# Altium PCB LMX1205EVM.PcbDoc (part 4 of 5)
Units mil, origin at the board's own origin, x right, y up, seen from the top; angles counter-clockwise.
Board outline 5000 x 5000 mil, 6 copper layers (Top Layer, RF GND, Signal Layer 3, Signal Layer 4, Signal Layer 5, Bottom Layer), stack 61.6 mil thick; 176 components, 99 nets, 572 pads, 2473 vias.
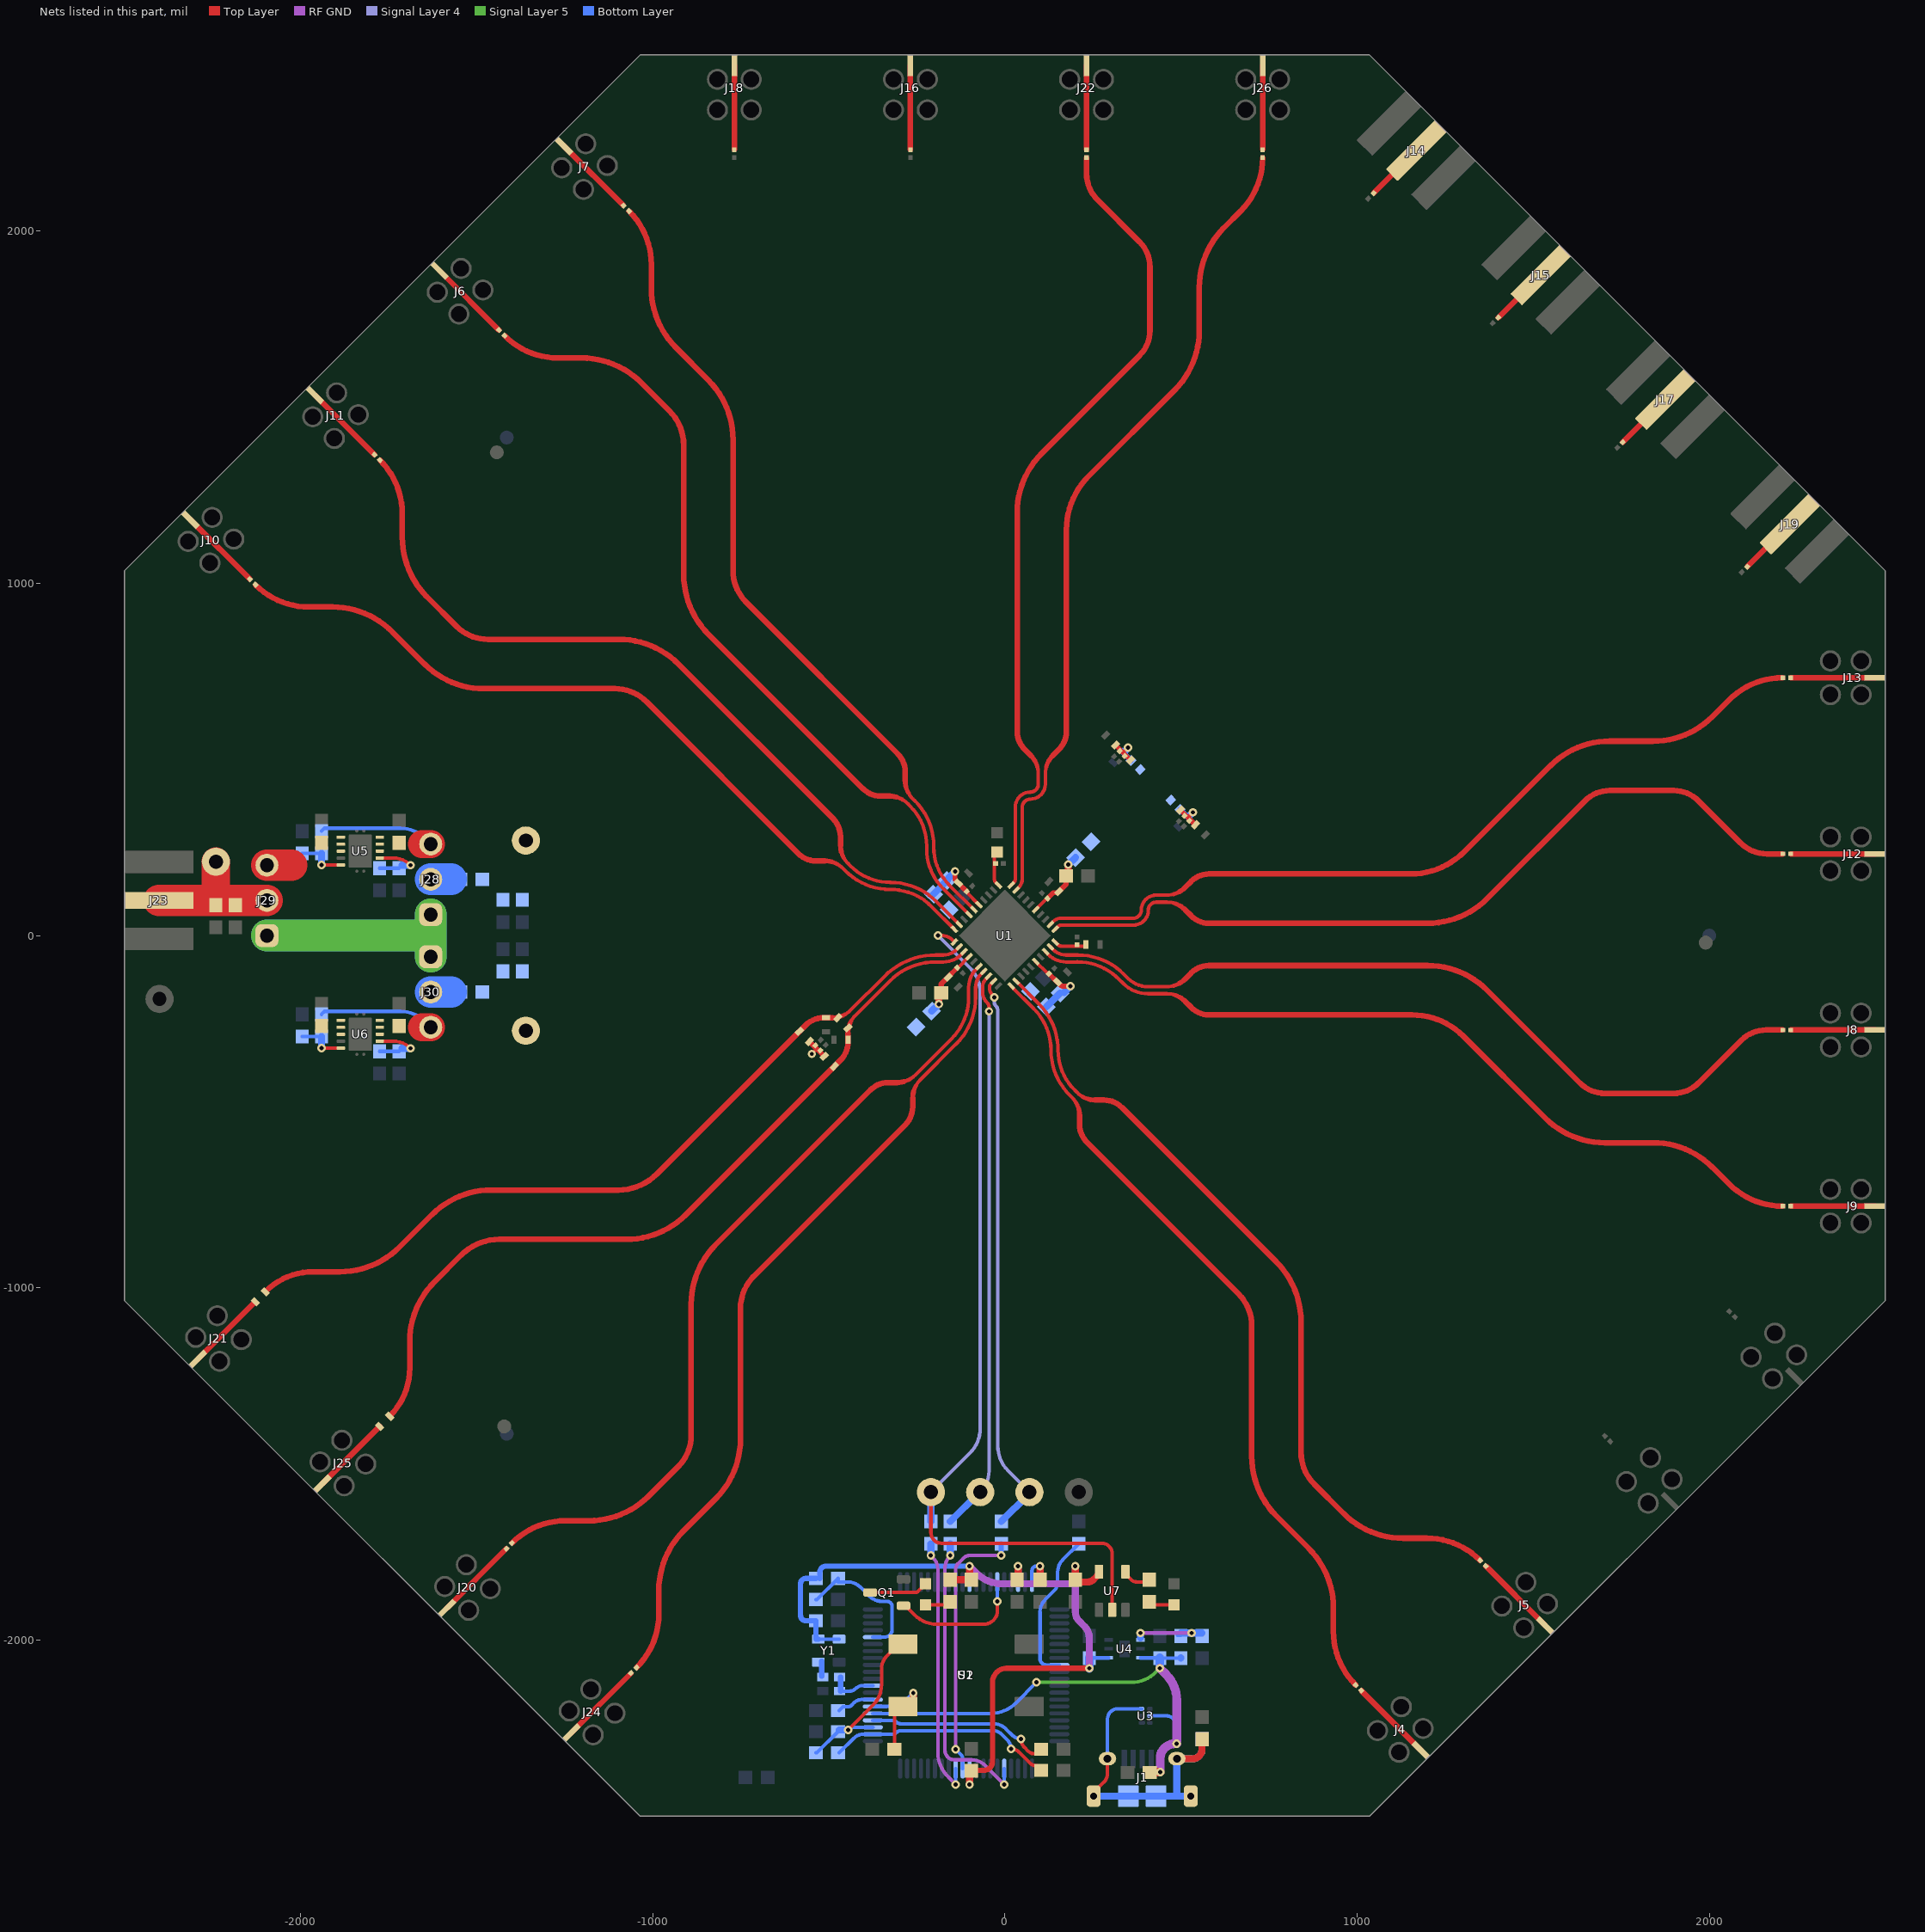
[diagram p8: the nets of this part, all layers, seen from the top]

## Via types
v1: diameter 24, hole 12, Top Layer to Bottom Layer, tented both sides, 2320 vias
v2: diameter 28, hole 16, Top Layer to Bottom Layer, 120 vias
v3: diameter 19.68, hole 7.87, Top Layer to Bottom Layer, tented both sides, 29 vias
v4: diameter 24, hole 12, Top Layer to Bottom Layer, tented bottom, 3 vias
v5: diameter 236.22, hole 157.48, Top Layer to Bottom Layer, tented both sides, 1 vias

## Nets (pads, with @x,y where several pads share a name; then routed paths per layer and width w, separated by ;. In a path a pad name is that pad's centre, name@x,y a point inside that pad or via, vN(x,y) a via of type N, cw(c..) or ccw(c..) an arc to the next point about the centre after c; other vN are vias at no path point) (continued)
NetC3_1: C3.1 C4.1 U1.31 | length 91.3
  Top Layer w10: C4.1@-29.67,230.48 -29.67,160.48 ccw(c-16.3,160.48) -25.75,151.03 U1.31@-18.1,143.37
NetC5_1: C5.1 C6.1 U1.20 | length 95.5
  Top Layer w10: U1.20@143.37,-18.1 151.03,-25.75 ccw(c160.48,-16.3) 160.48,-29.67 230,-29.67 C6.1@230,-25
NetC8_1: C8.1 C9.1 C70.2 L4.2 U1.25 | length 201.5
  Top Layer w10: U1.25@87.69,73.77 C8.1@120.1,106.18
  Top Layer w14: C8.1@120.93,105.34 137.2,121.61 C9.1@149.89,121.61 ; C70.2@173.56,169.71 C70.2@180.31,169.71
  Top Layer w15: C9.1@153.44,125.16 173.56,145.28 C70.2@173.56,169.71
  Top Layer w20: C70.2@180.31,169.71 v1(180.31,201.53)
  Bottom Layer w20: v1(180.31,201.53) L4.2@200.47,221.68
NetC10_1: C10.1 C11.1 C71.2 L3.2 U1.4 | length 197
  Top Layer w10: C10.1@-134.02,-92.26 U1.4@-101.61,-59.85
  Top Layer w14: C11.1@-161.95,-118.07 -161.24,-117.36 C10.1@-137.18,-93.34
  Top Layer w15: C71.2@-180.64,-162.63 -180.64,-137.5 C11.1@-160.87,-117.73
  Top Layer w20: v1(-187.38,-194.45) -187.38,-169.38 C71.2@-180.64,-162.63
  Bottom Layer w20: L3.2@-207.54,-214.61 v1(-187.38,-194.45)
NetC12_1: C12.1 C13.1 C68.2 L2.2 U1.35 | length 204.8
  Top Layer w10: C12.1@-109.71,127.39 -109.71,126.65 -109.71,125.14 -109.71,123.63 U1.35@-73.77,87.69
  Top Layer w14: v1(-141.42,182) -141.42,161.66 ccw(c-133.86,161.66) C13.1@-139.21,156.31 ; C13.1@-139.29,156.23 -132.25,149.18 -109.71,126.65 C12.1@-108.2,125.14
  Bottom Layer w20: L2.2@-202.58,117.73 C68.2@-163.69,156.62 ; C68.2@-159.1,164.32 v1(-141.42,182)
NetC14_1: C14.1 C15.1 C69.2 L1.2 U1.16 | length 200.2
  Top Layer w10: U1.16@87.69,-73.77 C14.1@120.1,-106.18
  Top Layer w14: C14.1@125.14,-108.2 C15.1@148.81,-131.88
  Top Layer w15: C15.1@149.55,-131.88 157.91,-140.24 ccw(c167,-131.15) 167,-144 v1(186,-144)
  Bottom Layer w20: L1.2@117.73,-202.58 C69.2@156.62,-163.69 ; C69.2@168.32,-161.68 v1(186,-144)
NetC16_2: C16.2 C58.2 C60.1 L7.2 R31.1 R35.2 | length 125.3
  Top Layer w10: 520.45,336.6 v1(533.87,350.02)
  Top Layer w14: R31.1@498.51,357.09 R35.2@540.94,314.66
  Bottom Layer w15: L7.2@497.59,358.01 C60.1@519.72,335.88
  Bottom Layer w20: C60.1@523.26,339.41 v1(533.87,350.02)
NetC17_1: C17.1 U1.37 | length 2332
  Top Layer w10: -290.77,386.28 cw(c-326.98,323.55) -275.77,374.77 -268.7,367.69 cw(c-381.84,254.56) -221.84,254.56 -221.84,245.94 ccw(c-62.83,245.94) -175.27,133.51 U1.37@-101.61,59.85
  Top Layer w12: -308.24,393.51 cw(c-326.98,323.55) -290.77,386.28
  Top Layer w14: -326.98,395.98 cw(c-326.98,323.55) -308.24,393.51
  Top Layer w16: C17.1@-1419.88,1702.72 ccw(c-1268.63,1853.96) -1268.63,1640.07 -1202.08,1640.07 cw(c-1202.08,1400.07) -1032.38,1569.78 -951.98,1489.38 cw(c-1049.09,1392.26) -911.75,1392.26 -911.75,1025.3 ccw(c-671.75,1025.3) -841.46,855.6 -403.05,417.19 ccw(c-351.84,468.41) -351.84,395.98 -326.98,395.98
NetC17_2: C17.2 J6.1 | length 238
  Top Layer w16: J6.1@-1605.13,1887.98 C17.2@-1436.84,1719.68
NetC18_1: C18.1 U1.36 | length 2332
  Top Layer w10: -273.14,403.91 ccw(c-210.42,440.12) -261.63,388.91 -254.56,381.84 cw(c-381.84,254.56) -201.84,254.56 -201.84,250.52 ccw(c-50.71,250.52) -157.57,143.66 U1.36@-87.69,73.77
  Top Layer w12: -280.37,421.38 ccw(c-210.42,440.12) -273.14,403.91
  Top Layer w14: -282.84,440.12 ccw(c-210.42,440.12) -280.37,421.38
  Top Layer w16: C18.1@-1066.32,2056.27 cw(c-1217.56,1905.03) -1003.68,1905.03 -1003.68,1838.48 ccw(c-763.68,1838.48) -933.38,1668.77 -842.05,1577.44 cw(c-1011.75,1407.73) -771.75,1407.73 -771.75,1037 ccw(c-643.51,1037) -734.19,946.32 -304.06,516.19 cw(c-355.27,464.97) -282.84,464.97 -282.84,440.12
NetC18_2: C18.2 J7.1 | length 238
  Top Layer w16: J7.1@-1251.58,2241.53 C18.2@-1083.29,2073.24
NetC19_1: C19.1 J8.1 | length 238
  Top Layer w16: C19.1@2232,-268 J8.1@2470,-268
NetC19_2: C19.2 U1.19 | length 2332
  Top Layer w10: U1.19@129.45,-32.01 137.11,-39.67 ccw(c174.4,-2.38) 174.4,-55.12 207.3,-55.12 cw(c207.3,-239.55) 337.72,-109.14 350.15,-121.57 ccw(c406.72,-65) 406.72,-145 460,-145 ccw(c460,-72.57) 478.75,-142.53
  Top Layer w12: 478.75,-142.53 ccw(c460,-72.57) 496.21,-135.3
  Top Layer w14: 496.21,-135.3 ccw(c460,-72.57) 511.21,-123.79
  Top Layer w16: 511.21,-123.79 528.79,-106.21 cw(c580,-157.43) 580,-85 1200,-85 cw(c1200,-325) 1369.71,-155.29 1633.12,-418.71 ccw(c1703.83,-348) 1703.83,-448 1898.58,-448 ccw(c1898.58,-348) 1969.29,-418.71 2090.71,-297.29 cw(c2161.42,-368) 2161.42,-268 C19.2@2208,-268
NetC20_1: C20.1 J9.1 | length 238
  Top Layer w16: C20.1@2232,-768 J9.1@2470,-768
NetC20_2: C20.2 U1.18 | length 2332
  Top Layer w10: U1.18@115.53,-45.93 123.19,-53.59 ccw(c174.4,-2.38) 174.4,-74.8 205.73,-74.8 cw(c205.73,-242.27) 324.15,-123.85 336.01,-135.71 ccw(c406.72,-65) 406.72,-165 460,-165 cw(c460,-237.43) 478.75,-167.47
  Top Layer w12: 478.75,-167.47 cw(c460,-237.43) 496.21,-174.7
  Top Layer w14: 496.21,-174.7 cw(c460,-237.43) 511.21,-186.21
  Top Layer w16: 511.21,-186.21 528.79,-203.79 ccw(c580,-152.57) 580,-225 1156.3,-225 cw(c1156.3,-430.5) 1301.61,-285.19 1534.13,-517.71 ccw(c1703.83,-348) 1703.83,-588 1840,-588 cw(c1840,-828) 2009.71,-658.29 2056.77,-705.36 ccw(c2208,-554.13) C20.2@2208,-768
NetC21_2: C21.2 C57.2 C59.1 L6.2 R29.1 R33.2 | length 125.3
  Top Layer w10: 336.6,520.45 v1(350.02,533.87)
  Top Layer w14: R29.1@314.66,540.94 R33.2@357.09,498.51
  Bottom Layer w15: C59.1@335.88,519.72 L6.2@358.01,497.59
  Bottom Layer w20: C59.1@339.41,523.26 v1(350.02,533.87)
NetC23_1: C23.1 J12.1 | length 238
  Top Layer w16: C23.1@2232,232 J12.1@2470,232
NetC23_2: C23.2 U1.21 | length 2332
  Top Layer w10: U1.21@143.37,18.1 151.03,25.75 cw(c160.48,16.3) 160.48,29.67 364.67,29.67 ccw(c364.67,72.5) 407.5,72.5 cw(c430,72.5) 430,95 460,95 cw(c460,22.57) 478.75,92.53
  Top Layer w12: 478.75,92.53 cw(c460,22.57) 496.21,85.3
  Top Layer w14: 496.21,85.3 cw(c460,22.57) 511.21,73.79
  Top Layer w16: 511.21,73.79 528.79,56.21 ccw(c580,107.43) 580,35 1200,35 ccw(c1200,275) 1369.71,105.29 1647.12,382.71 cw(c1717.83,312) 1717.83,412 1898.58,412 cw(c1898.58,312) 1969.29,382.71 2089.1,262.9 ccw(c2163.7,337.49) 2163.7,232 C23.2@2208,232
NetC24_1: C24.1 J13.1 | length 238
  Top Layer w16: C24.1@2232,732 J13.1@2470,732
NetC24_2: C24.2 U1.22 | length 2332
  Top Layer w10: U1.22@129.45,32.01 137.11,39.67 cw(c160.48,16.3) 160.48,49.35 364.35,49.35 ccw(c364.35,72.5) 387.5,72.5 cw(c430,72.5) 430,115 460,115 ccw(c460,187.43) 478.75,117.47
  Top Layer w12: 478.75,117.47 ccw(c460,187.43) 496.21,124.7
  Top Layer w14: 496.21,124.7 ccw(c460,187.43) 511.21,136.21
  Top Layer w16: 511.21,136.21 528.79,153.79 cw(c580,102.57) 580,175 1152.4,175 ccw(c1152.4,389.92) 1304.37,237.95 1548.13,481.71 cw(c1717.83,312) 1717.83,552 1840,552 ccw(c1840,792) 2009.71,622.29 2056.77,669.36 cw(c2207.99,518.15) C24.2@2207.99,732
NetC25_1: C25.1 J14.1 | length 169.7
  Top Layer w16: C25.1@1047.93,2108.59 J14.1@1167.91,2228.57
NetC26_1: C26.1 J15.1 | length 169.7
  Top Layer w16: C26.1@1401.49,1755.04 J15.1@1521.46,1875.02
NetC27_1: C27.1 J16.1 | length 238
  Top Layer w16: C27.1@-268,2232 J16.1@-268,2470
NetC28_1: C28.1 J17.1 | length 169.7
  Top Layer w16: C28.1@1755.04,1401.49 J17.1@1875.02,1521.46
NetC29_1: C29.1 J18.1 | length 238
  Top Layer w16: C29.1@-768,2232 J18.1@-768,2470
NetC30_1: C30.1 J19.1 | length 169.7
  Top Layer w16: C30.1@2108.59,1047.93 J19.1@2228.57,1167.91
NetC31_1: C31.1 J20.1 | length 238
  Top Layer w16: J20.1@-1583.92,-1909.19 C31.1@-1415.63,-1740.9
NetC31_2: C31.2 U1.6 | length 2332
  Top Layer w10: -269.56,-407.49 ccw(c-305.77,-344.77) -254.56,-395.98 -152.03,-293.45 ccw(c-271.26,-174.22) -102.64,-174.22 -102.64,-146.56 cw(c-30.22,-146.56) -81.43,-95.35 U1.6@-73.77,-87.69
  Top Layer w12: -287.03,-414.73 ccw(c-305.77,-344.77) -269.56,-407.49
  Top Layer w14: -305.77,-417.19 ccw(c-305.77,-344.77) -287.03,-414.73
  Top Layer w16: C31.2@-1398.66,-1723.93 cw(c-1247.43,-1875.16) -1247.43,-1661.28 -1180.87,-1661.28 ccw(c-1180.87,-1421.28) -1011.16,-1590.99 -927.16,-1506.99 ccw(c-1015.57,-1418.58) -890.54,-1418.58 -890.54,-1046.52 cw(c-650.54,-1046.52) -820.24,-876.81 -381.84,-438.41 cw(c-330.62,-489.62) -330.62,-417.19 -305.77,-417.19
NetC32_1: C32.1 J22.1 | length 238
  Top Layer w16: C32.1@232,2232 J22.1@232,2470
NetC33_1: C33.1 J24.1 | length 238
  Top Layer w16: J24.1@-1230.37,-2262.74 C33.1@-1062.07,-2094.45
NetC33_2: C33.2 U1.7 | length 2332
  Top Layer w10: -251.93,-425.12 cw(c-189.2,-461.34) -240.42,-410.12 -138.02,-307.73 ccw(c-270.97,-174.79) -82.96,-174.79 -82.96,-146.56 cw(c-30.22,-146.56) -67.51,-109.27 U1.7@-59.85,-101.61
  Top Layer w12: -259.16,-442.59 cw(c-189.2,-461.34) -251.93,-425.12
  Top Layer w14: -261.63,-461.34 cw(c-189.2,-461.34) -259.16,-442.59
  Top Layer w16: C33.2@-1045.1,-2077.48 ccw(c-1196.33,-1926.25) -982.46,-1926.25 -982.46,-1859.69 cw(c-742.46,-1859.69) -912.17,-1689.99 -820.83,-1598.65 ccw(c-990.54,-1428.94) -750.54,-1428.94 -750.54,-1058.22 cw(c-622.29,-1058.22) -712.98,-967.53 -282.84,-537.4 ccw(c-334.06,-486.19) -261.63,-486.19 -261.63,-461.34
NetC34_1: C34.1 J26.1 | length 238
  Top Layer w16: C34.1@732,2232 J26.1@732,2470
NetC35_1: C35.1 C36.1 J23.1 J29.2 TP2.1 | length 420.2
  Top Layer w20: C35.1@-2240,96.5 C35.1@-2240,100
  Top Layer w80: C35.1@-2240,100 TP2.1@-2240,210
  Top Layer w90: J23.1@-2401.67,100 -2240,100 J29.2@-2095,100
NetC38_1: C38.1 J1.6 J1.7 J1.8 J1.9 J1.10 J1.11 R15.2 U3.3 | length 952.9
  Top Layer w10: J1.9@252.2,-2442.91 252.2,-2432.8 280.68,-2404.32 ccw(c254.33,-2378) 291.57,-2378 J1.7@291.57,-2336.61
  Top Layer w20: J1.6@488.43,-2336.61 533.39,-2336.61 ccw(c533.39,-2310) 560,-2310 R15.2@560,-2281.5
  Bottom Layer w10: J1.7@291.57,-2336.61 291.58,-2223.74 cw(c320,-2223.74) 320,-2195.31 U3.3@388.19,-2195.32
  Bottom Layer w20: J1.9@252.2,-2442.91 J1.8@527.8,-2442.91 ; 488.43,-2436.61 J1.6@488.43,-2336.61 533.39,-2336.61 ccw(c533.39,-2310) 560,-2310 C38.1@560,-2281.5
NetC42_1: C42.1 R18.1 U4.4 | length 229
  RF GND w10: v1(385,-1980) v1(530,-1980)
  Bottom Layer w10: R18.1@490,-1987.01 R18.1@500,-1987.01
  Bottom Layer w20: 385,-1994 v1(385,-1980) ; R18.1@500,-1980 v1(530,-1980) C42.1@560,-1980
NetC44_1: C44.1 R19.1 U2.76 | length 410.6
  Bottom Layer w10: C44.1@-536.5,-1885 -533.5,-1885 R19.1@-473.5,-1825 -473.5,-1835 -445,-1835 cw(c-445,-1883.28) -410.86,-1849.14 -385,-1875 ccw(c-348.79,-1838.79) -348.79,-1890 -335,-1890 cw(c-335,-1905) -320,-1905 -320,-1970 cw(c-341.73,-1970) -341.73,-1991.73 U2.76@-374.76,-1991.73
NetC45_1: C45.1 S1.3 U2.66 | length 277.8
  Top Layer w10: C45.1@-313.5,-2310 S1.3@-313.5,-2195.61
  Top Layer w20: S1.3@-260,-2186.63 v1(-260,-2150)
  Bottom Layer w10: U2.66@-374.76,-2188.58 -336.67,-2188.58 ccw(c-336.67,-2096.62) -271.65,-2161.65 v1(-260,-2150)
NetC49_1: C49.1 U2.20 | length 102.7
  Top Layer w20: C49.1@100,-1830 C49.1@100,-1828.5 v1(100,-1790)
  Bottom Layer w10: U2.20@77.01,-1835.24 77.01,-1802.99 cw(c90,-1802.99) 90,-1790 v1(100,-1790)
NetC50_1: C50.1 U2.67 | length 106.3
  Bottom Layer w10: C50.1@-469.99,-2200.01 -459.03,-2189.05 -444.74,-2189.05 ccw(c-444.74,-2175.26) -434.99,-2185.01 -427.36,-2177.38 cw(c-406.9,-2197.85) -406.9,-2168.91 U2.67@-374.76,-2168.9
NetC52_1: C52.1 J28.3 R26.2 U5.8 U5.9 U5.10 | length 352.9
  Top Layer w80: J28.3@-1655,260 J28.3@-1630,260
  Bottom Layer w10: R26.2@-1940,296.5 -1931.5,305 -1716.42,305 cw(c-1716.42,205) -1645.71,275.71 J28.3@-1630,260
NetC55_1: C55.1 R40.2 U5.7 | length 184.8
  Top Layer w9.45: U5.7@-1774.88,220.32 -1736.05,220.32 cw(c-1736.05,150.95) v1(-1687,200)
  Bottom Layer w9.45: C55.1@-1720,191.5 C55.1@-1711.5,200
  Bottom Layer w10: R40.2@-1775,191.5 C55.1@-1720,191.5
  Bottom Layer w20: C55.1@-1711.5,200 v1(-1687,200)
NetC61_1: C61.1 J30.3 R41.2 U6.8 U6.9 U6.10 | length 352.9
  Top Layer w80: J30.3@-1655,-260 J30.3@-1630,-260
  Bottom Layer w10: R41.2@-1940,-223.5 -1931.5,-215 -1716.42,-215 cw(c-1716.42,-315) -1645.71,-244.29 J30.3@-1630,-260
NetC64_1: C64.1 R44.2 U6.7 | length 184.8
  Top Layer w9.45: U6.7@-1774.88,-299.69 -1736.04,-299.69 cw(c-1736.04,-369.04) v1(-1687,-320)
  Bottom Layer w10: R44.2@-1775,-328.5 C64.1@-1720,-328.5 C64.1@-1711.5,-320
  Bottom Layer w20: C64.1@-1711.5,-320 v1(-1687,-320)
NetD1_1: D1.1 R1.1 | length 72.1
  Top Layer w10: R1.1@410,-1891.5 ccw(c429.39,-1872.11) 429.39,-1899.53 D1.1@480,-1899.53
NetD2_1: D2.1 R17.1 | length 72.7
  Top Layer w10: D2.1@-225,-1899.53 -161.54,-1899.53 R17.1@-155,-1892.99
NetD2_2: D2.2 Q1.3 | length 166.8
  Top Layer w10: Q1.3@-382.24,-1865 -255,-1865 ccw(c-255,-1851.79) -245.67,-1861.14 D2.2@-225,-1840.47
NetJ4_1: J4.1 R20.1 | length 238
  Top Layer w16: R20.1@1012.58,-2143.95 J4.1@1180.87,-2312.24
NetJ5_1: J5.1 R4.1 | length 238
  Top Layer w16: R4.1@1366.13,-1790.39 J5.1@1534.42,-1958.69
NetJ10_1: J10.1 R6.2 | length 238
  Top Layer w16: J10.1@-2312.24,1180.87 R6.2@-2143.95,1012.58
NetJ11_1: J11.1 R10.2 | length 238
  Top Layer w16: J11.1@-1958.69,1534.42 R10.2@-1790.39,1366.13
NetJ21_1: J21.1 R3.1 | length 229.4
  Top Layer w16: J21.1@-2291.03,-1202.08 R3.1@-2128.82,-1039.87
NetJ25_1: J25.1 R9.1 | length 229.4
  Top Layer w16: J25.1@-1937.47,-1555.64 R9.1@-1775.26,-1393.42
NetJ28_2: J28.2 L5.1 | length 58
  Bottom Layer w90: J28.2@-1630,160 -1572,160
NetJ30_2: J30.2 L9.1 | length 58
  Bottom Layer w90: J30.2@-1630,-160 -1572,-160
NetQ1_1: Q1.1 U2.15 | length 378.9
  Top Layer w10: Q1.1@-280,-1905 -256.69,-1928.31 ccw(c-192.25,-1863.87) -192.25,-1955 -60,-1955 ccw(c-60,-1916) -21,-1916 v1(-21,-1890)
  Bottom Layer w10: v1@-21.42,-1888.99 U2.15@-21.42,-1835.24
  Bottom Layer w11: v1@-21.42,-1888.99 ccw(c-19.99,-1888.99) v1(-21,-1890)
NetR1_2: R1.2 U7.4 | length 89
  Top Layer w10: U7.4@342.4,-1805.87 342.4,-1812.4 357.93,-1827.93 ccw(c375,-1810.86) 375,-1835 410,-1835 R1.2@410,-1828.5
NetR2_1: R2.1 R7.1 R9.2 R11.2 U1.3 | length 2322.6
  Top Layer w10: -435.77,-241.27 cw(c-373.05,-277.49) -424.26,-226.27 -326.76,-128.77 cw(c-196.47,-259.07) -196.47,-74.8 -174.4,-74.8 ccw(c-174.4,-2.38) -123.19,-53.59 U1.3@-115.53,-45.93
  Top Layer w12: R7.1@-443.01,-258.74 cw(c-373.05,-277.49) -435.77,-241.27
  Top Layer w14: -445.48,-277.49 cw(c-373.05,-277.49) R7.1@-443.01,-258.74
  Top Layer w16: R9.2@-1746.13,-1364.29 ccw(c-1882.68,-1227.74) -1689.57,-1227.74 -1689.57,-1152.58 cw(c-1449.57,-1152.58) -1619.27,-982.88 -1543.68,-907.29 cw(c-1434.96,-1016.01) -1434.96,-862.25 -1074.8,-862.25 ccw(c-1074.8,-622.25) -905.1,-791.96 -466.69,-353.55 ccw(c-517.9,-302.34) -445.48,-302.34 -445.48,-277.49
NetR3_2: R3.2 R5.2 R7.2 R8.1 U1.2 | length 2322.6
  Top Layer w10: -453.41,-223.64 ccw(c-489.62,-160.92) -438.41,-212.13 -341.58,-115.31 cw(c-196.27,-260.63) -196.27,-55.12 -174.4,-55.12 ccw(c-174.4,-2.38) -137.11,-39.67 U1.2@-129.45,-32.01
  Top Layer w12: R7.2@-470.87,-230.88 ccw(c-489.62,-160.92) -453.41,-223.64
  Top Layer w14: -489.62,-233.35 ccw(c-489.62,-160.92) R7.2@-470.87,-230.88
  Top Layer w16: R3.2@-2099.68,-1010.74 cw(c-1963.14,-1147.29) -1963.14,-954.18 -1887.98,-954.18 ccw(c-1887.98,-714.18) -1718.27,-883.88 -1626.93,-792.55 cw(c-1457.23,-962.25) -1457.23,-722.25 -1097.7,-722.25 ccw(c-1097.7,-566.97) -987.9,-676.77 -565.69,-254.56 cw(c-514.47,-305.77) -514.47,-233.35 -489.62,-233.35
NetR4_2: R4.2 U1.12 | length 2332
  Top Layer w10: U1.12@32.01,-129.45 96.89,-194.32 cw(c-34.06,-325.27) 151.13,-325.27 ccw(c311.13,-325.27) 197.99,-438.41 205.06,-445.48 ccw(c256.27,-394.26) 220.06,-456.99
  Top Layer w12: 220.06,-456.99 ccw(c256.27,-394.26) 237.53,-464.22
  Top Layer w14: 237.53,-464.22 ccw(c256.27,-394.26) 256.27,-466.69
  Top Layer w16: 256.27,-466.69 281.13,-466.69 cw(c281.13,-539.12) 332.34,-487.9 770.75,-926.31 cw(c601.04,-1096.02) 841.04,-1096.02 841.04,-1467.57 ccw(c967.28,-1467.57) 878.01,-1556.84 961.66,-1640.49 ccw(c1131.37,-1470.78) 1131.37,-1710.78 1197.93,-1710.78 cw(c1197.93,-1924.65) R4.2@1349.16,-1773.42
NetR6_1: R6.1 U1.40 | length 2332
  Top Layer w10: -474.62,202.43 cw(c-510.83,139.71) -459.62,190.92 -452.55,183.85 ccw(c-325.27,311.13) -325.27,131.13 cw(c-325.27,-35.13) -207.71,82.43 U1.40@-143.37,18.1
  Top Layer w12: -492.09,209.66 cw(c-510.83,139.71) -474.62,202.43
  Top Layer w14: -510.83,212.13 cw(c-510.83,139.71) -492.09,209.66
  Top Layer w16: R6.1@-2126.92,995.54 ccw(c-1975.84,1146.62) -1975.84,932.97 -1909.19,932.96 cw(c-1909.19,692.96) -1739.48,862.67 -1648.15,771.34 ccw(c-1478.44,941.04) -1478.44,701.04 -1106.92,701.04 cw(c-1106.92,574.73) -1017.6,664.04 -586.9,233.35 ccw(c-535.69,284.56) -535.69,212.13 -510.83,212.13
NetR10_1: R10.1 U1.39 | length 2332
  Top Layer w10: -456.99,220.06 ccw(c-394.26,256.27) -445.48,205.06 -438.41,197.99 ccw(c-325.27,311.13) -325.27,151.13 cw(c-325.27,-34.06) -194.32,96.89 U1.39@-129.45,32.01
  Top Layer w12: -464.22,237.53 ccw(c-394.26,256.27) -456.99,220.06
  Top Layer w14: -466.69,256.27 ccw(c-394.26,256.27) -464.22,237.53
  Top Layer w16: R10.1@-1773.43,1349.16 cw(c-1924.67,1197.92) -1710.78,1197.92 -1710.78,1131.37 ccw(c-1470.78,1131.37) -1640.49,961.67 -1556.84,878.01 ccw(c-1467.56,967.3) -1467.56,841.03 -1096.02,841.04 cw(c-1096.02,601.04) -926.31,770.75 -487.9,332.34 cw(c-539.12,281.13) -466.69,281.13 -466.69,256.27
NetR12_1: R12.1 U2.29 | length 431.1
  Bottom Layer w10: U2.29@154.76,-2070.47 117.48,-2070.47 cw(c117.48,-2052.99) 100,-2052.99 100,-1920 cw(c148.28,-1920) 114.14,-1885.86 140,-1860 ccw(c115.86,-1835.86) 150,-1835.86 150,-1807.15 cw(c199.86,-1807.15) 164.6,-1771.89 R12.1@210,-1726.5
NetR13_1: R13.1 U2.45 | length 848.4
  RF GND w10: v1(-155,-1760) ccw(c-118.79,-1796.21) -170,-1796.21 -170,-2312.93 ccw(c-142.93,-2312.93) -142.93,-2340 -95,-2340 cw(c-95,-2396.17) -55.28,-2356.45 v1(-1.73,-2410)
  Bottom Layer w10: v1(-1.73,-2410) -1.73,-2408.27 U2.45@-1.73,-2364.76
  Bottom Layer w11: v1@-1.73,-2408.27 v1@0,-2410
  Bottom Layer w20: v1(-155,-1760) R13.1@-155,-1726.5
NetR14_1: R14.1 U2.51 | length 756.6
  RF GND w10: v1(-140,-2310) -140,-1800 cw(c-115.86,-1800) -132.93,-1782.93 -117.07,-1767.07 cw(c-100,-1784.14) -100,-1760 v1(-10,-1760)
  Bottom Layer w10: v1(-140,-2310) -124.14,-2325.86 cw(c-134.51,-2336.23) -119.84,-2336.23 U2.51@-119.84,-2364.76 U2.51@-120,-2364.61
  Bottom Layer w15: v1(-10,-1760) R14.1@-10,-1726.5
NetR16_1: R16.1 U2.52 | length 752.9
  RF GND w10: v1(-210,-1760) -204.14,-1765.86 cw(c-238.28,-1800) -190,-1800 -190,-2318.11 ccw(c-90,-2318.11) -160.71,-2388.82 v1(-139.53,-2410)
  Bottom Layer w10: v1@-140,-2410 -139.76,-2409.76 v1@-139.53,-2409.53 ; U2.52@-140,-2365.24 U2.52@-139.53,-2364.76 v1@-139.53,-2409.53 ; v1(-139.53,-2410) v1@-139.53,-2409.53
  Bottom Layer w20: v1(-210,-1760) R16.1@-210,-1726.5
NetR20_2: R20.2 U1.11 | length 2332
  Top Layer w10: U1.11@18.1,-143.37 82.43,-207.71 cw(c-35.13,-325.27) 131.13,-325.27 ccw(c311.13,-325.27) 183.85,-452.55 190.92,-459.62 cw(c139.71,-510.83) 202.43,-474.62
  Top Layer w12: 202.43,-474.62 cw(c139.71,-510.83) 209.66,-492.09
  Top Layer w14: 209.66,-492.09 cw(c139.71,-510.83) 212.13,-510.83
  Top Layer w16: 212.13,-510.83 212.13,-535.69 ccw(c284.56,-535.69) 233.35,-586.9 663.55,-1017.1 cw(c573.04,-1107.62) 701.04,-1107.61 701.04,-1478.44 ccw(c941.04,-1478.44) 771.34,-1648.15 862.67,-1739.48 cw(c692.96,-1909.19) 932.96,-1909.19 932.96,-1975.75 ccw(c1146.83,-1975.75) R20.2@995.61,-2126.98
NetR21_2: R21.2 U2.64 | length 532.2
  Top Layer w10: v1(45.96,-2280.42) ccw(c81.58,-2280.42) 56.39,-2305.6 65.56,-2314.77 ccw(c85.43,-2294.9) 85.43,-2323 103.5,-2323 R21.2@103.5,-2310 R21.2@103.05,-2310.45
  Bottom Layer w10: U2.64@-374.76,-2227.95 -330,-2227.95 -319.31,-2227.95 cw(c-319.31,-2243.95) -308,-2232.64 ccw(c-295.93,-2220.57) -295.93,-2237.64 -31.46,-2237.64 cw(c-31.46,-2287.13) 3.54,-2252.14 21.82,-2270.42 ccw(c45.96,-2246.28) v1(45.96,-2280.42)
NetR22_2: R22.2 R23.2 U2.62 | length 624.7
  Top Layer w10: v1(17.68,-2308.7) cw(c17.68,-2340.84) 40.4,-2318.11 71.71,-2349.42 ccw(c90,-2331.13) R22.2@90,-2357
  Bottom Layer w10: R23.2@-470,-2320 -428.36,-2278.36 cw(c-401.71,-2305.02) U2.62@-401.71,-2267.32 ; U2.62@-399.39,-2267.32 U2.62@-374.76,-2267.32 -320.07,-2267.32 ccw(c-320.07,-2250.25) -308,-2262.32 cw(c-296.69,-2273.63) -296.69,-2257.64 -31.46,-2257.64 cw(c-31.46,-2287.13) -10.61,-2266.28 7.68,-2284.56 cw(c-16.46,-2308.7) v1(17.68,-2308.7)
NetR23_1: R23.1 R25.2 S1.1 U2.63 | length 493.4
  Top Layer w10: v1(-445,-2255) -373.89,-2183.89 ccw(c-431.56,-2126.22) -350,-2126.22 -350,-2081.21 cw(c-298.79,-2081.21) -335.01,-2045.01 -310.1,-2020.1 cw(c-289.13,-2041.07) S1.1@-289.13,-2011.42
  Bottom Layer w10: R23.1@-536.5,-2320 -533.5,-2320 R25.2@-473.5,-2260 ; v1(-445,-2255) cw(c-427.23,-2272.77) -427.23,-2247.64 U2.63@-374.76,-2247.64
  Bottom Layer w20: R25.2@-470,-2255 v1(-445,-2255)
NetR26_1: R26.1 R28.2 U5.5 | length 142.8
  Top Layer w9.45: v1(-1940,200.63) U5.5@-1885.12,200.63
  Bottom Layer w9.45: R28.2@-1995,233.5 R26.1@-1940,233.5
  Bottom Layer w20: v1(-1940,200.63) R26.1@-1940,233.5
NetR27_1: R27.1 Y1.3 | length 42.5
  Bottom Layer w15: R27.1@-520,-2102.52 Y1.3@-520,-2060
NetR41_1: R41.1 R43.2 U6.5 | length 142.7
  Top Layer w9.45: v1(-1940,-319.37) U6.5@-1885.12,-319.37
  Bottom Layer w10: R43.2@-1994.93,-286.5 R41.1@-1940,-286.5
  Bottom Layer w20: v1(-1940,-319.37) R41.1@-1940,-286.5
S2N: C34.2 U1.29 | length 2332
  Top Layer w10: U1.29@32.01,129.45 39.67,137.11 ccw(c16.3,160.48) 49.35,160.48 49.35,364.35 cw(c72.5,364.35) 72.5,387.5 ccw(c72.5,430) 115,430 115,460 cw(c187.43,460) 117.47,478.75
  Top Layer w12: 117.47,478.75 cw(c187.43,460) 124.7,496.21
  Top Layer w14: 124.7,496.21 cw(c187.43,460) 136.21,511.21
  Top Layer w16: 136.21,511.21 153.79,528.79 ccw(c102.57,580) 175,580 175,1152.29 cw(c390.18,1152.29) 238.02,1304.45 481.71,1548.13 ccw(c312,1717.83) 552,1717.83 552,1840 cw(c792,1840) 622.29,2009.71 669.36,2056.77 ccw(c518.13,2208) C34.2@732,2208
S2P: C32.2 U1.30 | length 2332
  Top Layer w10: U1.30@18.1,143.37 25.75,151.03 ccw(c16.3,160.48) 29.67,160.48 29.67,364.67 cw(c72.5,364.67) 72.5,407.5 ccw(c72.5,430) 95,430 95,460 ccw(c22.57,460) 92.53,478.75
  Top Layer w12: 85.3,496.21 cw(c22.57,460) 92.53,478.75
  Top Layer w14: 73.79,511.21 cw(c22.57,460) 85.3,496.21
  Top Layer w16: 73.79,511.21 56.21,528.79 cw(c107.43,580) 35,580 35,1200 cw(c275,1200) 105.29,1369.71 382.71,1647.12 ccw(c312,1717.83) 412,1717.83 412,1898.58 ccw(c312,1898.58) 382.71,1969.29 262.9,2089.1 cw(c337.5,2163.7) 232,2163.7 C32.2@232,2208
SCK: R13.2 TP5.1 U1.8 | length 1601.2
  Top Layer w10: U1.8@-45.93,-115.53 -53.59,-123.19 ccw(c-30.22,-146.56) -63.27,-146.56 -63.27,-158.94 ccw(c-19.33,-158.94) -50.4,-190.02 cw(c-63.44,-203.05) -45,-203.05 v1(-45,-215)
  Signal Layer 4 w10: TP5.1@-70,-1580 ccw(c-130.36,-1519.64) -45,-1519.64 v1(-45,-215)
  Bottom Layer w20: R13.2@-155,-1663.5 -72.55,-1581.06 cw(c-70,-1583.61) TP5.1@-70,-1580
SDI: R14.2 TP6.1 U1.9 | length 1610.8
  Top Layer w10: U1.9@-32.01,-129.45 -39.67,-137.11 ccw(c-30.22,-146.56) -43.59,-146.56 ccw(c-7.73,-146.56) -33.08,-171.92 v1(-30,-175)
  Signal Layer 4 w10: v1(-30,-175) -30,-187.93 ccw(c-12.93,-187.93) -25,-200 cw(c-37.07,-212.07) -20,-212.07 -20,-1448.58 ccw(c80,-1448.58) 9.29,-1519.29 TP6.1@70,-1580
  Bottom Layer w20: R14.2@-10,-1663.5 67.52,-1585.98 ccw(c61.54,-1580) TP6.1@70,-1580
SDO: R16.2 TP1.1 U1.1 U7.2 | length 2637.1
  Top Layer w10: TP1.1@-210,-1580 -210,-1695 ccw(c-180,-1695) -180,-1725 275,-1725 cw(c275,-1755) 305,-1755 U7.2@305,-1914.13 ; v1(-190,0) -176.78,0 cw(c-176.78,-36.97) -150.64,-10.83 U1.1@-144.37,-17.09
  Signal Layer 4 w10: TP1.1@-210,-1580 -99.29,-1469.29 ccw(c-170,-1398.58) -70,-1398.58 -70,-161.42 ccw(c-170,-161.42) -99.29,-90.71 v1(-190,0)
  Bottom Layer w20: R16.2@-210,-1663.5 TP1.1@-210,-1580
V0123: C53.2 C54.1 L1.1 L2.1 L5.2 TP7.1
VBUS: C37.1 C41.1 J1.1 R18.2 U2.65 U3.5 U4.6 | length 1630.1
  Top Layer w25: C37.1@411.5,-2375 v1(441.18,-2375)
  RF GND w25: v1(440,-2080) 458.71,-2098.71 cw(c388,-2169.42) 488,-2169.42 v1(488,-2294) 484.38,-2294 ccw(c484.38,-2338.38) 453,-2307 ccw(c481.53,-2335.53) 441.18,-2335.53 v1(441.18,-2375)
  Signal Layer 5 w10: v1(90,-2120) 358.58,-2120 ccw(c358.58,-2020) 429.29,-2090.71 v1(440,-2080)
  Bottom Layer w10: U2.65@-374.76,-2208.27 -39.69,-2208.27 ccw(c-39.69,-2108.27) 31.02,-2178.98 v1(90,-2120) ; U4.6@385.28,-2050.59 440,-2050.59 C41.1@440,-2050 ; U3.5@411.81,-2215 458,-2215 cw(c458,-2245) 488,-2245 488,-2290.38 cw(c484.38,-2290.38) 484.38,-2294 v1(488,-2294) ; J1.1@440,-2338.78 441,-2337.78 J1.1@441.18,-2337.6 J1.1@441.18,-2335.53 ; C41.1@440,-2051.5 R18.2@500,-2051.5
  Bottom Layer w15: v1(441.18,-2375) J1.1@441.18,-2337.6 ; J1.1@441.18,-2335.53 cw(c481.53,-2335.53) 453,-2307 cw(c484.38,-2338.38) v1@484.38,-2294
  Bottom Layer w20: R18.2@500,-2051.5 R18.2@500,-2050
  Bottom Layer w25: v1(440,-2080) C41.1@440,-2050.59
VCC_BYP: J28.1 J29.1 J30.1 | length 1170.4
  Signal Layer 5 w90: J29.1@-2095,0 -1630,0 ; J30.1@-1630,-60 -1630,0 ; J28.1@-1630,60 -1630,0
  Bottom Layer w20: -1631,0 -1630,1
  Bottom Layer w90: J29.1@-2095,0 -1631,0 ; J30.1@-1630,-60 -1630,1 J28.1@-1630,60
VCC_LDO: C51.1 C56.1 J29.3 U5.1 U5.2 U5.3 U6.1 U6.2 U6.3 | length 70
  Top Layer w90: J29.3@-2095,200 -2025,200
VDD: C7.1 C43.1 C46.1 C47.1 C48.1 C67.1 R17.2 R19.2 U2.11 U2.18 U2.50 U4.1 U7.5 Y1.1 Y1.4 | length 2551.2
  Top Layer w11: C67.1@200,-1835 C67.1@200,-1828.5 ; U7.5@267.6,-1812.4 U7.5@267.6,-1805.87
  Top Layer w15: C48.1@-85,-2370 -60,-2370 ccw(c-60,-2345) -35,-2345 -35,-2120 cw(c5,-2120) 5,-2080 v1(240,-2080)
  Top Layer w20: R17.2@-155,-1828.5 C47.1@-95,-1828.5 ; v1(-100.16,-2410) C48.1@-100.16,-2375 ; C47.1@-100.16,-1825 v1(-100.16,-1790) ; C48.1@-100,-2375 C48.1@-95,-2370 ; C46.1@35,-1830 C46.1@35,-1828.5 ; C46.1@37.64,-1828.5 v1(37.64,-1790) ; C67.1@200,-1835 235.81,-1835 ccw(c235.81,-1812.82) 251.5,-1828.5 U7.5@267.6,-1812.4 ; C67.1@200,-1828.5 v1(200,-1790)
  RF GND w20: v1(-100.16,-1790) -79.45,-1810.71 ccw(c-8.74,-1740) -8.74,-1840 37.64,-1840 ; v1(37.64,-1790) 37.64,-1840 ; v1(200,-1790) 200,-1840 ; v1(240,-2080) 240,-1995 ccw(c191.72,-1995) 225.86,-1960.86 210.61,-1945.61 cw(c236.21,-1920) 200,-1920 200,-1840 ; 37.64,-1840 200,-1840
  Bottom Layer w10: Y1.4@-529.53,-1997.52 Y1.1@-470.47,-1997.52 ; v1(-100.16,-2410) U2.50@-100.16,-2364.76 U2.50@-99.99,-2364.93 ; U2.11@-100.16,-1835.24 -100.16,-1790.16 -100.08,-1790.08 v1@-100,-1790 ; U2.18@37.64,-1835.24 v1(37.64,-1790) ; C43.1@240,-2050 240.59,-2050.59 U4.1@294.72,-2050.59
  Bottom Layer w11: v1@35,-1790 v1@37.64,-1792.64
  Bottom Layer w15: R19.2@-536.5,-1825 -565,-1825 ccw(c-565,-1840) -580,-1840 -580,-1930 ccw(c-565,-1930) -565,-1945 C7.1@-536.5,-1945 -536.5,-1997.52 Y1.4@-529.53,-1997.52 ; R19.2@-525,-1825 -525,-1806.97 cw(c-508.03,-1806.97) -508.03,-1790 v1(-100.16,-1790)
  Bottom Layer w25: v1(240,-2080) C43.1@240,-2051.5 C43.1@240,-2050
VLGC: C62.2 C63.1 C65.2 C66.2 L3.1 L4.1 L6.1 L7.1 L9.2 R2.2 R8.2 TP9.1 | length 80.5
  Top Layer w10: R8.2@-555.08,-300.52 ccw(c-551.58,-300.52) R8.2@-554.06,-302.99 ; v1(-548.01,-335.88) -537.4,-325.27 ; R2.2@-515.12,-341.92 ccw(c-512.65,-339.45) R2.2@-512.65,-342.95
  Top Layer w14: R8.2@-555.08,-300.52 R2.2@-512.65,-342.95
XIN: R27.2 R37.2 U2.69 | length 135.8
  Bottom Layer w10: R37.2@-466.38,-2145 -440.9,-2145 ccw(c-440.9,-2121.1) -424,-2138 cw(c-403.55,-2158.45) -403.55,-2129.53 U2.69@-374.76,-2129.53
  Bottom Layer w15: R37.2@-466.38,-2145 R27.2@-466.38,-2105
pads on no net: FID1.1 FID2.1 FID3.1 FID4.1 FID5.1 FID6.1 J1.4 S1.2 S1.4 SH-J1.0 SH-J2.0 SH-J3.0 U2.1 U2.2 U2.3 U2.4 U2.5 U2.6 U2.7 U2.8 U2.9 U2.10 U2.12 U2.13 U2.16 U2.17 U2.21 U2.22 U2.23 U2.24 U2.25 U2.26 U2.27 U2.28 U2.30 U2.31 U2.32 U2.33 U2.34 U2.35 U2.36 U2.37 U2.38 U2.39 U2.40 U2.41 U2.42 U2.43 U2.44 U2.46 U2.47 U2.48 U2.53 U2.54 U2.55 U2.56 U2.57 U2.58 U2.59 U2.60 U2.70 U2.71 U2.72 U2.73 U2.74 U2.75 U2.77 U2.78 U2.79 U2.80 U3.4 U4.2 U4.5 U4.7 U5.4 U6.4
copper on no net: | length 15.2
  Bottom Layer w10: -297,-2380.01 -297,-2364.77

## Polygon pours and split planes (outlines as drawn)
NetC16_2 on Top Layer "TOP_LAYER_NETC16_2_P275" (solid, pour order 275): 526.79,357.09 512.65,342.95 526.79,328.8 540.94,342.95
NetC21_2 on Top Layer "TOP_LAYER_NETC21_2_P273" (solid, pour order 273): 342.95,540.94 328.8,526.79 342.95,512.65 357.09,526.79
VLGC on Top Layer "TOP_LAYER_VLGC_P271" (solid, pour order 271): -537.4,-311.13 -555.08,-328.8 -540.94,-342.95 -523.26,-325.27
NetC35_1 on Top Layer "TOP_LAYER_NETC35_1_P080" (solid, pour order 80): -2395,145 -2500,145 -2500,55 -2395,55
VCC_LDO on Top Layer "TOP_LAYER_VCC_LDO_P078" (solid, remove dead copper, pour order 78): -1970,-236 -1970,235 -1876,235 -1875,236 -1875,283 -1876,284 -2019,284 -2040,263 -2040,-264 -2019,-285 -1876,-285 -1875,-284 -1875,-237 -1876,-236
no net on Top Layer "TOP_LAYER_NONET_P263" (solid, remove dead copper, pour order 263): -1901,284
NetC61_1 on Top Layer "TOP_LAYER_NETC61_1_P108" (solid, remove dead copper, pour order 108): -1786,-236 -1787,-237 -1787,-284 -1786,-285 -1640,-285 -1640,-236
NetC52_1 on Top Layer "TOP_LAYER_NETC52_1_P122" (solid, pour order 122): -1786,284 -1787,283 -1787,236 -1786,235 -1636,235 -1636,284
no net on Top Layer "TOP_LAYER_NONET_P261" (solid, remove dead copper, pour order 261): -1786,284
no net on Top Layer "TOP_LAYER_NONET_P260" (solid, remove dead copper, pour order 260): -1786,284
no net on Top Layer "TOP_LAYER_NONET_P258" (solid, remove dead copper, pour order 258): -1785,284
GND on Top Layer "TOP_LAYER_GND_P269" (solid, remove dead copper, pour order 269): -2500,1035.53 -1035.53,2500 1035.53,2500 2500,1035.54 2500,-1035.54 1035.54,-2500 -1035.54,-2500 -2500,-1035.53
DGND on Top Layer "TOP_LAYER_DGND_P126" (solid, remove dead copper, pour order 126): -600,-2500 -600,-1773.8 -546.2,-1720 546.2,-1720 600,-1773.8 600,-2500
no net on Top Layer "TOP_LAYER_NONET_P256" (solid, pour order 256): -1211.61,245.7
no net on Top Layer "TOP_LAYER_NONET_P254" (solid, remove dead copper, pour order 254): -1690.7,222.54
no net on Top Layer "TOP_LAYER_NONET_P142" (solid, remove dead copper, pour order 142): -1495.05,-827.35
V0123 on Bottom Layer "BOTTOM_LAYER_V0123_P134" (solid, pour order 134): -169.71,106.07 -104.65,41.01 -138.59,7.07 -138.59,-7.07 -7.07,-138.59 7.07,-138.59 41.01,-104.65 106.07,-169.71 74.25,-201.53 109.6,-236.88 -53.03,-399.52 -67.18,-399.52 -546.69,80 -1500,80 -1500,270 -1450,320 -1435.81,320 -447.28,320 -201.53,74.25
VLGC on Bottom Layer "BOTTOM_LAYER_VLGC_P128" (solid, pour order 128): 385.37,484.37 484.37,385.37 441.94,342.95 441.94,328.8 671.75,98.99 671.75,-35.36 -45.96,-753.07 -187.38,-753.07 -620.45,-320 -1450,-320 -1500,-270 -1500,-80 -407.9,-80 -60.1,-427.8 427.8,60.1 212.13,275.77 212.13,311.13
GND on Bottom Layer "BOTTOM_LAYER_GND_P282" (solid, remove dead copper, pour order 282): -2500,1035.53 -1035.53,2500 1035.53,2500 2500,1035.53 2500,-1035.53 1035.53,-2500 -1035.53,-2500 -2500,-1035.53
DGND on Bottom Layer "BOTTOM_LAYER_DGND_P278" (solid, remove dead copper, pour order 278): -600,-2500 -600,-1773.8 -546.2,-1720 546.2,-1720 600,-1773.8 600,-2500
VDD on Bottom Layer "BOTTOM_LAYER_VDD_P277" (solid, pour order 277): 255,-2065 255,-2040 310,-2040 310,-2065
VBUS on Bottom Layer "BOTTOM_LAYER_VBUS_P184" (solid, pour order 184): 370,-2065 370,-2040 425,-2040 425,-2065
no net on Bottom Layer "BOTTOM_LAYER_NONET_P280" (solid, remove dead copper, pour order 280): -141.98,61.25
no net on Bottom Layer "BOTTOM_LAYER_NONET_P164" (solid, remove dead copper, pour order 164): 444,-2185
no net on Bottom Layer "BOTTOM_LAYER_NONET_P136" (solid, remove dead copper, pour order 136): 430,-2186
GND on Signal Layer 5 "SIGNAL_LAYER_5_GND_P236" (solid, remove dead copper, pour order 236): -2500,1035.53 -1035.53,2500 1035.53,2500 2500,1035.53 2500,-1035.53 1035.53,-2500 -1035.53,-2500 -2500,-1035.53
DGND on Signal Layer 5 "SIGNAL_LAYER_5_DGND_P070" (solid, remove dead copper, pour order 70): -600,-2500 -600,-1773.8 -546.2,-1720 546.2,-1720 600,-1773.8 600,-2500
no net on Signal Layer 5 "SIGNAL_LAYER_5_NONET_P052" (solid, remove dead copper, pour order 52): -610,-2500
GND on RF GND "RF_GND_GND_P068" (solid, remove dead copper, pour order 68): -2500,1035.53 -1035.53,2500 1035.53,2500 2500,1035.53 2500,-1035.53 1035.53,-2500 -1035.53,-2500 -2500,-1035.53
DGND on RF GND "RF_GND_DGND_P054" (solid, remove dead copper, pour order 54): -600,-2500 -600,-1773.8 -546.2,-1720 546.2,-1720 600,-1773.8 600,-2500
no net on RF GND "RF_GND_NONET_P042" (solid, remove dead copper, pour order 42): -3959.8,141.42
no net on RF GND "RF_GND_NONET_P030" (solid, remove dead copper, pour order 30): -750,-2651.58
no net on M1 Board Outline "TOP_LAYER_NONET_P-001" (solid, remove dead copper): -1901,284
no net on M1 Board Outline "NONET_L-01_P-001" (solid, remove dead copper): 0,3535.53
DGND on Signal Layer 3 "SIGNAL_LAYER_3_DGND_P265" (solid, remove dead copper, pour order 265): -600,-2500 -600,-1773.8 -546.2,-1720 546.2,-1720 600,-1773.8 600,-2500
GND on Signal Layer 3 "SIGNAL_LAYER_3_GND_P240" (solid, remove dead copper, pour order 240): -2500,1035.53 -1035.53,2500 1035.53,2500 2500,1035.53 2500,-1035.53 1035.53,-2500 -1035.53,-2500 -2500,-1035.53
no net on Signal Layer 3 "SIGNAL_LAYER_3_NONET_P060" (solid, remove dead copper, pour order 60): -605,-1938.7
DGND on Signal Layer 4 "SIGNAL_LAYER_4_DGND_P267" (solid, remove dead copper, pour order 267): -600,-1773.8 -546.2,-1720 546.2,-1720 600,-1773.8 600,-2500 -600,-2500
GND on Signal Layer 4 "SIGNAL_LAYER_4_GND_P242" (solid, remove dead copper, pour order 242): -2500,1035.53 -1035.53,2500 1035.53,2500 2500,1035.53 2500,-1035.53 1035.53,-2500 -1035.53,-2500 -2500,-1035.53
no net on Top Solder "NONET_L-01_P-001" (solid, remove dead copper): 161.35,96
no net on Top Solder "NONET_L-01_P-001" (solid, remove dead copper): 201,124
no net on Top Solder "NONET_L-01_P-001" (solid, remove dead copper): 265,68
no net on Top Solder "NONET_L-01_P-001" (solid): 2500,-816 2205,-816 2205,-720 2500,-720
no net on Top Solder "NONET_L-01_P-001" (solid): 2500,-316 2208.98,-316 2208.98,-220 2500,-220
no net on Top Solder "NONET_L-01_P-001" (solid): 2500,184 2208.98,184 2208.98,280 2500,280
no net on Top Solder "NONET_L-01_P-001" (solid): 2500,684 2208.98,684 2208.98,780 2500,780
no net on Top Solder "NONET_L-01_P-001" (solid): 684,2208.98 684,2500 780,2500 780,2208.98
no net on Top Solder "NONET_L-01_P-001" (solid): 184,2205 184,2500 280,2500 280,2205
no net on Top Solder "NONET_L-01_P-001" (solid): -316,2208.98 -316,2500 -220,2500 -220,2208.98
no net on Top Solder "NONET_L-01_P-001" (solid): -816,2205 -816,2500 -720,2500 -720,2205
no net on Top Solder "NONET_L-01_P-001" (solid): 1168.14,-2367.39 962.36,-2161.61 1030.24,-2093.73 1236.02,-2299.51
no net on Top Solder "NONET_L-01_P-001" (solid): 1521.69,-2013.84 1315.91,-1808.06 1383.79,-1740.17 1589.58,-1945.96
no net on Top Solder "NONET_L-01_P-001" (solid): 1875.25,-1660.29 1669.46,-1454.5 1737.34,-1386.62 1943.13,-1592.4
no net on Top Solder "NONET_L-01_P-001" (solid): 2228.8,-1306.73 2023.02,-1100.95 2090.9,-1033.07 2296.68,-1238.85
no net on Top Solder "NONET_L-01_P-001" (solid): -1100.95,2023.02 -1306.73,2228.8 -1238.85,2296.68 -1033.07,2090.9
no net on Top Solder "NONET_L-01_P-001" (solid): -1454.5,1669.46 -1660.29,1875.25 -1592.4,1943.13 -1386.62,1737.34
no net on Top Solder "NONET_L-01_P-001" (solid): -2161.61,962.36 -2367.39,1168.14 -2299.51,1236.02 -2093.73,1030.24
no net on Top Solder "NONET_L-01_P-001" (solid): -1808.06,1315.91 -2013.84,1521.69 -1945.96,1589.58 -1740.17,1383.79
no net on Top Solder "NONET_L-01_P-001" (solid): 1704.82,1419.15 1910.6,1624.93 1978.48,1557.05 1772.7,1351.26
no net on Top Solder "NONET_L-01_P-001" (solid): 997.71,2126.25 1203.5,2332.04 1271.38,2264.16 1065.59,2058.37
no net on Top Solder "NONET_L-01_P-001" (solid): 1351.26,1772.7 1557.05,1978.48 1624.93,1910.6 1419.15,1704.82
no net on Top Solder "NONET_L-01_P-001" (solid): 2058.37,1065.59 2264.16,1271.38 2332.04,1203.5 2126.25,997.71
no net on Top Solder "NONET_L-01_P-001" (solid): -1285.52,-2250.01 -1079.74,-2044.23 -1011.85,-2112.11 -1217.64,-2317.9
no net on Top Solder "NONET_L-01_P-001" (solid): -1639.07,-1896.46 -1433.29,-1690.68 -1365.41,-1758.56 -1571.19,-1964.34
no net on Top Solder "NONET_L-01_P-001" (solid): -1992.63,-1542.91 -1780.49,-1330.77 -1712.61,-1398.66 -1924.74,-1610.79
no net on Top Solder "NONET_L-01_P-001" (solid): -2346.18,-1189.35 -2134.05,-977.22 -2066.17,-1045.1 -2278.3,-1257.24
no net on Top Solder (solid): 1439.61,1700.72
no net on Top Solder (solid): 1106.97,2067.52
no net on Top Solder (solid): 1094.63,2188.7
no net on Top Solder (solid): 1082.95,2177.01
no net on Top Solder "NONET_L-01_P-001" (solid, remove dead copper): -1839.15,-1459.53
no net on Top Solder "NONET_L-01_P-001" (solid, remove dead copper): -2208.38,-1114.31

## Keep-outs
Keep-Out Layer:
  text ".Layer_Name" at -2823,-4858.49 h60

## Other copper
Top Layer:
  pour cut-out: 1181.95,2353.35 1292.94,2242.94 1146.4,2096.4 1035.7,2207.1
  pour cut-out: -480.83,-254.56 -466.69,-268.7 -459.62,-261.63 -473.76,-247.49
  pour cut-out: -2128.39,-1011.16
  pour cut-out: -2115.66,-995.61 -2084.55,-1026.72 -2112.84,-1055 -2143.95,-1023.89
  pour cut-out: -1762.11,-1349.16 -1731,-1380.27 -1759.28,-1408.56 -1790.39,-1377.44
  pour cut-out: 175,-2185 215,-2145 405,-2145 445,-2185 445,-2270 430,-2285 315,-2285 305,-2295 305,-2335 290,-2350 290,-2395 272,-2413 -23,-2413 -23,-2255 175,-2255
  pour cut-out: -390.84,858.06
  pour cut-out: -404.47,825.9
  pour cut-out: -429.69,865.31
  pour cut-out: -1409.26,-1709.08 -1430.48,-1730.29 -1405.02,-1755.75 -1383.81,-1734.53
  pour cut-out: -1055.71,-2062.63 -1076.92,-2083.84 -1051.47,-2109.3 -1030.25,-2088.09
  pour cut-out: -600,-2500 -600,-1773.8 -546.2,-1720 546.2,-1720 600,-1773.8 600,-2500 650,-2500 650,-1753.09 566.91,-1670 -566.91,-1670 -650,-1753.09 -650,-2500
  pour cut-out: -1072,330
  pour cut-out: 2261,146
  pour cut-out: 1535.18,1999.99 1646.87,1888.87 1500.4,1742.4 1388.99,1853.81
  pour cut-out: 1889.08,1646.08 1999.87,1535.87 1853.4,1389.4 1742.9,1499.9
  pour cut-out: 2242.63,1292.53 2353.32,1182.42 2206.85,1035.95 2096.45,1146.35
  pour cut-out: 2205,214 2205,250 2235,250 2235,214
  pour cut-out: 2205,714 2205,750 2235,750 2235,714
  pour cut-out: 2076.77,1041.57 2097.99,1062.78 2123.44,1037.33 2102.23,1016.11
  pour cut-out: 1723.22,1395.12 1744.43,1416.33 1769.89,1390.88 1748.68,1369.67
  pour cut-out: 1369.67,1748.68 1390.88,1769.89 1416.33,1744.43 1395.12,1723.22
  pour cut-out: 1016.11,2102.23 1037.33,2123.44 1062.78,2097.99 1041.57,2076.77
  pour cut-out: 714,2235 750,2235 750,2205 714,2205
  pour cut-out: 214,2235 250,2235 250,2205 214,2205
  pour cut-out: -286,2235 -250,2235 -250,2205 -286,2205
  pour cut-out: -786,2235 -750,2235 -750,2205 -786,2205
  pour cut-out: -1072.68,2088.09 -1051.47,2066.87 -1076.92,2041.42 -1098.14,2062.63
  pour cut-out: -1426.23,1734.53 -1405.02,1713.32 -1430.48,1687.86 -1451.69,1709.08
  pour cut-out: -1779.79,1380.98 -1758.57,1359.77 -1784.03,1334.31 -1805.24,1355.52
  pour cut-out: -2133.34,1027.43 -2112.13,1006.21 -2137.58,980.76 -2158.8,1001.97
  pour cut-out: 1006.21,-2112.13 1027.43,-2133.34 1001.97,-2158.8 980.76,-2137.58
  pour cut-out: 1359.77,-1758.57 1380.98,-1779.79 1355.52,-1805.24 1334.31,-1784.03
  pour cut-out: 1713.32,-1405.02 1734.53,-1426.23 1709.08,-1451.69 1687.86,-1430.48
  pour cut-out: 2066.87,-1051.47 2088.09,-1072.68 2062.63,-1098.14 2041.42,-1076.92
  pour cut-out: 2205,-750 2235,-750 2235,-786 2205,-786
  pour cut-out: 2205,-250 2235,-250 2235,-286 2205,-286
  pour cut-out: -368,-190
  pour cut-out: 99.92,-38.34
  region: -158,-339
  pour cut-out: 360,-2160
  text ".Layer_Name" at -2823,-4858.49 h60
RF GND:
  pour cut-out: 1035.7,2207.1 1182.08,2353.48 1292.78,2242.78 1146.4,2096.4
  pour cut-out: 1388.99,1853.81 1535.37,2000.18 1646.78,1888.78 1500.4,1742.4
  pour cut-out: 1742.9,1499.9 1889.28,1646.28 1999.78,1535.78 1853.4,1389.4
  pour cut-out: 2096.45,1146.35 2242.83,1292.73 2353.23,1182.33 2206.85,1035.95
  pour cut-out: -600,-2500 -600,-1773.8 -546.2,-1720 546.2,-1720 600,-1773.8 600,-2500 650,-2500 650,-1753.09 566.91,-1670 -566.91,-1670 -650,-1753.09 -650,-2500
  pour cut-out: -550,-2625
  pour cut-out: -537.4,-2625
  text ".Layer_Name" at -2823,-4858.49 h60
Signal Layer 5:
  pour cut-out: -600,-2500 -600,-1773.8 -546.2,-1720 546.2,-1720 600,-1773.8 600,-2500 650,-2500 650,-1753.09 566.91,-1670 -566.91,-1670 -650,-1753.09 -650,-2500
  pour cut-out: -548.01,-2675
  text ".Layer_Name" at -2823,-4858.49 h60
Signal Layer 3:
  pour cut-out: -600,-2500 -600,-1773.8 -546.2,-1720 546.2,-1720 600,-1773.8 600,-2500 650,-2500 650,-1753.09 566.91,-1670 -566.91,-1670 -650,-1753.09 -650,-2500
  text ".Layer_Name" at -2660.16,-4870 h60
Signal Layer 4:
  pour cut-out: -600,-2500 -600,-1773.8 -546.2,-1720 546.2,-1720 600,-1773.8 600,-2500 650,-2500 650,-1753.09 566.91,-1670 -566.91,-1670 -650,-1753.09 -650,-2500
  text ".Layer_Name" at -2689,-4825 h60
Bottom Layer:
  pour cut-out: -703.19,-2361.3 -766,-2361.3 -766,-2375 -780.26,-2375 cw(c-780.26,-2290.01) -840.35,-2350.11 -2360.11,-830.35 cw(c-2300.01,-770.26) -2385,-770.26 -2385,-205 -2415,-205 -2415,-776.46 ccw(c-2315,-776.46) -2385.71,-847.17 -861.58,-2371.3 -861.58,-2371.32 -857.19,-2375.71 ccw(c-786.48,-2305) -786.48,-2405 -766,-2405 -766,-2418.7 -703.19,-2418.7
  pour cut-out: -2643,-462
  pour cut-out: -248.82,-215.31 -250.81,-217.29 -210.22,-257.88 -208.23,-255.89
  pour cut-out: -90,-2380 -90,-2400 -70,-2400 -70,-2380
  pour cut-out: 65,-1825 65,-1800 50,-1800 50,-1825
  pour cut-out: -457.29,-2165
  pour cut-out: -390,-2140 -390,-2160 -420,-2160 -420,-2140
  pour cut-out: 500,-2295
  pour cut-out: 347,-2290 347,-2402 297,-2402 297,-2419 365,-2419 365,-2290
  pour cut-out: -271.9,-1799.5
  pour cut-out: -600,-2500 -600,-1773.8 -546.2,-1720 546.2,-1720 600,-1773.8 600,-2500 650,-2500 650,-1753.09 566.91,-1670 -566.91,-1670 -650,-1753.09 -650,-2500
  pour cut-out: -2580.94,-1449.57
  pour cut-out: -2625,-400
  pour cut-out: -2625,-400
  pour cut-out: -625,-2600
  pour cut-out: -640.95,-2600
  pour cut-out: -370,-2210 20,-2210 93,-2283 93,-2335 -345,-2335 -370,-2310
  text ".Layer_Name" at -2823,-4858.49 h60

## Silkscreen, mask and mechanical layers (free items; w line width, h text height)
Top Overlay:
  lines w6: -295.71,596.95 -287.16,590.74 ; -295.54,643.64 -287.16,590.74 ; -281.51,598.52 -287.16,590.74 ; 612.81,-306.91 607.16,-299.13 ; 615.72,-292.92 607.16,-299.13 ; 660.07,-307.51 607.16,-299.13
  lines w10: -166.17,-10.61 -176.78,0 -166.17,10.61 ; -1998.71,1169.13 -1929.22,1097.99 -1902.12,1195.01 -1998.71,1169.13 ; -1951.61,-1145.51 -1925.73,-1242.11 -1854.6,-1172.61 -1951.61,-1145.51 ; 1124.3,-1972.83 1220.89,-1946.95 1151.4,-1875.81 1124.3,-1972.83
  lines w15: -2040,100 -2010,100 -2010,200 -2040,200 ; -1985,0 -1955,0 -1955,100 -1985,100 ; -1575,-160 -1545,-160 -1545,-60 -1575,-60 ; -1575,160 -1545,160 -1545,260 -1575,260 ; -1520,-260 -1490,-260 -1490,-160 -1520,-160 ; -1520,60 -1490,60 -1490,160 -1520,160
  text "!" at -1958.69,1145.51 h70 r315
  text "DC-couple" at -1909.19,1117.23 h30 r315
  text "LDO" at -1525,185 h30
  text "LDO" at -1990,125 h30
  text "VCCIN" at -1470,85 h30
  text "VCCIN" at -1935,25 h30
  text "VCCIN" at -1525,-85 h30
  text "LDO" at -1470,-185 h30
  text "DC-couple" at -1873.83,-1152.58 h30 r45
  text "!" at -1902.12,-1202.08 h70 r45
  text "DC-couple" at 1131.37,-1895.05 h30 r135
  text "!" at 1180.87,-1923.33 h70 r135
  text ".Layer_Name" at -2823,-4858.49 h60
Bottom Overlay:
  circle w10: c358.5,-2240 r1.8
  text ".Layer_Name" at -2823,-4858.49 h60
Top Paste:
  text ".Layer_Name" at -2823,-4858.49 h60
Bottom Paste:
  text ".Layer_Name" at -2823,-4858.49 h60
Top Solder:
  pour cut-out: 368.03,641.26
  pour cut-out: 208.04,141.14
  pour cut-out: 1131,-522
  pour cut-out: 1156,-507
  lines w21: -207.71,82.43 -168.11,42.83 ; -194.32,96.89 -154.73,57.29 ; -175.27,133.51 -127.18,85.42 ; -174.4,-74.8 ccw(c-174.4,-2.38) -143.79,-68.02 ; -174.4,-55.12 ccw(c-174.4,-2.38) -159.86,-53.07 ; -157.57,143.66 -113.03,99.11 ; -102.64,-146.56 cw(c-30.22,-146.56) -95.86,-115.95 ; -82.96,-146.56 cw(c-30.22,-146.56) -80.65,-131.14 ; -74.8,174.4 ccw(c-2.38,174.4) -68.02,143.79 ; -55.12,174.46 ccw(c-2.23,174.46) -52.81,159 ; 29.67,182 29.67,202 ; 42.83,-168.11 82.43,-207.71 ; 49.35,163 49.35,191 ; 57.29,-154.73 96.89,-194.32 ; 68.64,142.28 ccw(c-25.92,201.37) 85.59,201.37 ; 83.36,128.5 ccw(c-24.41,201.19) 105.59,201.19 ; 84.99,-126.75 127.41,-169.17 ; 98.36,-112.29 140.79,-154.71 ; 128.5,83.36 cw(c201.19,-24.41) 201.19,105.59 ; 142.24,68.58 cw(c201.53,-26.3) 201.53,85.59 ; 143.79,-68.02 ccw(c174.4,-2.38) 174.4,-74.8 ; 158.98,-52.81 ccw(c174.4,-2.38) 174.4,-55.12 ; 183,29.67 213,29.67
  lines w38: 29.67,214.67 29.67,364.67 ; 49.35,204.35 49.35,364.35 ; 204.35,49.35 364.35,49.35 ; 214.67,29.67 364.67,29.67
  lines w40: -649.12,-298.4 -585.48,-234.76 cw(c-514.47,-305.77) -514.47,-205.35 -489.62,-205.35 ; -510.53,-436.99 -446.89,-373.35 ccw(c-517.9,-302.34) -417.48,-302.34 -417.48,-277.49 ; -489.62,-206.35 ccw(c-489.62,-160.92) -477.86,-204.8 ; -477.6,-205.76 ccw(c-489.62,-160.92) -466.41,-201.13 ; -418.48,-277.49 cw(c-373.05,-277.49) -416.93,-265.73 ; -417.9,-265.47 cw(c-373.05,-277.49) -413.26,-254.27 ; 215.27,452.26 ccw(c175.06,475.48) 219.91,463.46 ; 218.94,463.72 ccw(c175.06,475.48) 220.49,475.48 ; 219.49,475.48 219.49,500.33 cw(c319.91,500.33) 248.9,571.34 312.54,634.98 ; 268.42,399.11 cw(c291.63,358.91) 279.61,403.75 ; 279.87,402.79 cw(c291.63,358.91) 291.63,404.33 ; 291.63,403.34 316.48,403.34 ccw(c316.48,503.76) 387.49,432.75 451.13,496.39 ; 399.11,268.42 ccw(c358.91,291.63) 403.75,279.61 ; 402.79,279.87 ccw(c358.91,291.63) 404.33,291.63 ; 403.34,291.63 403.34,316.48 cw(c503.76,316.48) 432.75,387.49 496.39,451.13 ; 452.26,215.27 cw(c475.48,175.06) 463.46,219.91 ; 463.72,218.94 cw(c475.48,175.06) 475.48,220.49 ; 474.15,219.4 499,219.4 ; 500.33,219.49 ccw(c500.33,319.91) 571.34,248.9 634.98,312.54
  lines w96: -987.9,-676.77 -627.27,-316.15 ; -905.1,-791.96 -530.33,-417.19 ; 331.28,614.12 698.97,981.82 ; 432.77,517.62 804,888.85 ; 519.72,434.87 890.95,806.1 ; 614.19,331.35 981.89,699.05
  text ".Layer_Name" at -2823,-4858.49 h60
  text ".Layer_Name" at -2823,-4858.49 h60
Bottom Solder:
  circle w10: c-1237.44,-1237.44 r145
  circle w10: c1237.44,-1237.44 r145
  circle w10: c1237.44,1237.44 r145
  circle w10: c-1237.44,1237.44 r145
  text ".Layer_Name" at -2823,-4858.49 h60
Drill Guide:
  text ".Layer_Name" at -2823,-4858.49 h60
M1 Board Outline:
  the board outline again, w10
M2 Board Dimensions:
  rectangle: -3400,-4275 -3275,-4150
  rectangle: -3275,-4400 -2900,-4275
  lines w7: -3400,-4275 -2400,-4275 ; -3275,-4400 -3275,-4150 ; -3150,-4400 -3150,-4150 ; -2900,-4400 -2900,-4150 ; -2650,-4400 -2650,-4150 ; -3400,-4400 -2400,-4400 -2400,-4150 -3400,-4150 -3400,-4400
M3 3D STEP Top:
  text ".Layer_Name" at -2823,-4858.49 h60
M4 3D STEP Bottom:
  text ".Layer_Name" at -2823,-4858.49 h60
M5 Assembly Top:
  circle w10: c-1036.92,359 r4.92
  circle w10: c-187.57,-2.03 r4.92
  circle w10: c-1044.03,-166.41 r4.92
  circle w10: c-1851.09,-59.83 r4.92
  circle w10: c-2200,169.44 r5.52
  lines w6: -2150,150 -2250,150 -2250,-50 -2150,-50 -2150,150 ; -2150,150 -2150,150
  lines w10: -3692,-4930.17 2908,-4930.17 ; -3692,-4726.83 2910,-4726.83 ; -3692,-4523.5 -3692,-5133.5 313,-5133.5 2910,-5133.5 2910,-4523.5 -3691.5,-4523.5 -3691.5,-5133.5 -2116,-5133.5 ; -1227,-5133.5 -1227,-4523.5 ; 40,-4726.83 40,-4523.5 ; 880,-4726.83 880,-4523.5 ; 1502,-5140 1502,-4937.17
  text "COMPONENTS MARKED 'DNP' SHOULD NOT BE POPULATED." at -2246.5,-4318.5 h60
  text "ASSEMBLY VARIANT:" at -2247,-4434 h60
  text ".VariantName" at -1211,-4434 h60
  text "PCB VIEWED FROM TOP SIDE" at -3628.5,-4655.67 h60
  text "BOARD #:" at -1152,-4655.67 h60
  text ".PRJ_Number" at -606.5,-4655.67 h60
  text "REV:" at 238,-4655.67 h60
  text ".PCB_Rev" at 529.5,-4655.67 h60
  text "SVN REV:" at 1076,-4655.67 h60
  text ".VersionControl_RevNumber" at 1582,-4655.67 h60
  text "Layer Name =" at -3617,-4852 h60
  text "TID #:" at -1152,-4859 h60
  text ".TID" at -606.5,-4859 h60
  text ".Layer_Name" at -2772,-4870 h60
  text "PLOT NAME =" at -3628.5,-5064.34 h60
  text ".plot_File_Name" at -2823,-5064.34 h60
  text "GENERATED    :" at -1150,-5064.34 h60
  text ".Print_Date" at -280.5,-5064.34 h60
  text ".Print_Time" at 448.5,-5064.34 h60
